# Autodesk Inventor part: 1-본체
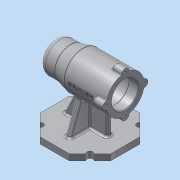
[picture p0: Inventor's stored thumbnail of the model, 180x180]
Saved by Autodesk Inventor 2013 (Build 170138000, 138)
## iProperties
Created: 2019-12
Part Number: 1-본체
Material: 알루미늄 6061
Document SubType Name: Modeling
Designer: Administrator
Density: 2.71 g/cm^3
Mass: 728.497 g
Surface Area: 714.69 cm^2
Volume: 268.818 cm^3
Author: Administrator
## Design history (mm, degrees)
sketch "스케치1" dims "d0" = 112
  geometry: L1 (23.196, 56)-(56, 23.196); L2 (56, 23.196)-(56, -23.196); L3 (56, -23.196)-(23.196, -56); L4 (23.196, -56)-(-23.196, -56); L5 (-23.196, -56)-(-56, -23.196); L6 (-56, -23.196)-(-56, 23.196); L7 (-56, 23.196)-(-23.196, 56); L8 (-23.196, 56)-(23.196, 56); C1 r 5 at (-39.598, 39.598); C2 r 5 at (-39.598, -39.598); C3 r 5 at (39.598, -39.598); C4 r 5 at (39.598, 39.598); 4 further points
  constraints: 16 end point, 5 midpoint, 4 centre point, 3 equal radius, 2 coincident, 2 vertical alignment, 19 other
  dimensions: "d2" = 10 diameter of C1
extrude "돌출1" new body sketch "스케치1" distance "d3" = 10; taper "d4" = 0 deg
extrude "돌출2" cut sketch "스케치1" distance "d5" = 10; taper "d6" = 0 deg
sketch "스케치2"
  geometry: L1 (-56, 80)-(56, 80); L2 (56, 101)-(41, 101); L3 (41, 101)-(41, 104); L4 (41, 104)-(-13, 104); L5 (-13, 104)-(-13, 101); L6 (-13, 101)-(-25, 101); L7 (-25, 101)-(-25, 97.5); L8 (-25, 97.5)-(-43, 97.5); L9 (-43, 97.5)-(-43, 96); L10 (-43, 96)-(-47, 96); L11 (-47, 96)-(-47, 90.5); L12 (-47, 90.5)-(-50, 90.5); L13 (-50, 90.5)-(-50, 80); L14 (-56, 80)-(-56, 105); L15 (-56, 105)-(-31, 105); L16 (-31, 105)-(-11, 110); L17 (-11, 110)-(56, 110); L18 (56, 110)-(56, 101); 2 further points
  constraints: 36 end point, 12 parallel, 2 horizontal, 2 perpendicular, 2 vertical alignment, 1 collinear, 1 point on line
  dimensions: "d7" = 112 distance of L1.start L1.end; "d9" = 80 distance from line of L1 point (0, 0); "d10" = 15 distance of L2.start L2.end; "d11" = 54 distance of L3.end L4.end; "d12" = 3 distance of L11.end L12.end; "d13" = 4 distance of L9.end L10.end; "d14" = 12 distance of L5.end L6.end; "d15" = 18 distance of L7.end L8.end; "d16" = 25 distance from line of L15.end L14; "d17" = 45 distance from line of L16.end L14; "d19" = 42 diameter of L2 L1; "d20" = 48 diameter of L4 L1; "d21" = 42 diameter of L6 L1; "d22" = 21 diameter of L12 L1; "d23" = 32 diameter of L10 L1; "d24" = 35 diameter of L8 L1; "d25" = 60 diameter of L17 L1; "d26" = 50 diameter of L15 L1
revolve "회전1" sketch "스케치2" stored, may be unused: angle "d27" = 90 deg
sketch "스케치3"
  geometry: C1 r 21 at (0, 0) reference; C2 r 6 at (0, -30); 2 further points
  constraints: 2 vertical alignment, 1 centre point, 1 other
  dimensions: "d28" = 12 diameter of C2
extrude "돌출3" join sketch "스케치3" distance "d30" = 16; taper "d31" = 0 deg
sketch "스케치4"
  geometry: A1 r 6 centre (0, 0) between (-5.97, 0.6) and (5.97, 0.6) reference; 2 further points
  constraints: 1 coincident
hole "구멍1" sketch "스케치4" at (0, 0) diameter "d32" = 3.242; stored, may be unused: countersink angle "d36" = 90 deg, drill point angle "d38" = 118 deg; dims "d33" = 8, "d34" = 4, "d35" = 2, "d37" = 11
sketch "스케치5"
  geometry: L1 (23.196, 56)-(-23.196, 56) reference; L2 (-4, 0)-(4, 0); L3 (4, 0)-(4, 31); L4 (4, 31)-(-4, 31); L5 (-4, 31)-(-4, 0); 2 further points
  constraints: 8 end point, 2 midpoint, 2 parallel, 1 horizontal, 1 perpendicular, 1 vertical alignment
  dimensions: "d42" = 8 distance of L3.end L4.end; "d44" = 25 distance between parallel lines of L4 L1
extrude "돌출4" join sketch "스케치5" stored distance "d45" = 16; taper "d46" = 0 deg
sketch "스케치6"
  geometry: L1 (-31, 55)-(-11, 50) reference; L2 (-11, 50)-(40, 50) reference; L3 (-23.196, 10)-(-36.062, 10) reference; L4 (23.196, 10)-(-23.196, 10) reference; L5 (-43.134, 10)-(-34.598, 10) reference; L6 (-43.134, 10)-(-56, 10) reference; L7 (-18.476, 51.869)-(-38, 10); 1 further point
  constraints: 2 end point, 2 point on line
  dimensions: "d47" = 18 distance of L7.end L6.end; "d48" = 115 deg angle of L7 L6
feature "리브1" sketch "스케치6" dims "d49" = 1, "d50" = 8, "d51" = 0, "d52" = 0, "d53" = 1, "d54" = 1
sketch "스케치7"
  geometry: L1 (23.196, 10)-(-23.196, 10) reference; L2 (36.062, 10)-(23.196, 10) reference; L3 (34.598, 10)-(43.134, 10) reference; L4 (-23.196, 10)-(-36.062, 10) reference; L5 (-43.134, 10)-(-34.598, 10) reference; L6 (-43.134, 10)-(-56, 10) reference; L7 (56, 10)-(43.134, 10) reference; L8 (18.979, 56.766)-(36, 10); A1 r 30 centre (0, 80) between (4, 50.268) and (-4, 50.268) reference; 1 further point
  constraints: 2 end point, 1 point on circle, 1 point on line
  dimensions: "d55" = 20 distance of L8.end L7.start; "d56" = 110 deg angle of L3 L8
feature "리브2" sketch "스케치7" dims "d57" = 1, "d58" = 8, "d59" = 0, "d60" = 0, "d61" = 1, "d62" = 1
node "작업 평면1"
sketch "스케치8"
  geometry: L1 (33.5, 5.97)-(33.5, 29.4) reference; L2 (17.5, 6)-(17.5, -6) reference; 5 further points
  constraints: 1 horizontal alignment, 1 midpoint, 1 other
  dimensions: "d63" = 41 distance from line of point (-7.5, 0) L1
feature "엠보싱1" sketch "스케치8" dims "d64" = 0.5, "d65" = 0
fillet "모깎기1" dims "d66" = 0.3
fillet "모깎기2" dims "d67" = 1, "d68" = 3
fillet "모깎기4" dims "d70" = 3
fillet "모깎기5" dims "d71" = 3
fillet "모깎기6" dims "d72" = 3
fillet "모깎기7" dims "d73" = 3
chamfer "모따기1" distance "d74" = 1; stored, may be unused: second distance "d75" = 2, angle "d76" = 45 deg
fillet "모깎기8" dims "d77" = 3
fillet "모깎기9" dims "d78" = 10
node "솔리드1"
pattern_circular "원형 패턴1" dims angle "d40" = 360 deg
mirror "대칭1"
